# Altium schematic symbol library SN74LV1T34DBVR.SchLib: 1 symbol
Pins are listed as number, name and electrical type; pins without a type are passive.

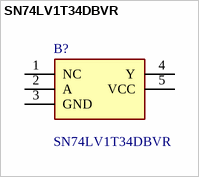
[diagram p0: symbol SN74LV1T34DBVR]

## SN74LV1T34DBVR
designator B?
Single Power Supply BUFFER Logic Level Shifter (no enable); Manufacturer_Name: Texas Instruments; Geometry.Height: 1.45mm
footprint SOT95P280X145-5N
pins: 1 NC, 2 A, 3 GND, 4 Y, 5 VCC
